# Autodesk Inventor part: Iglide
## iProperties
Author: cdotson
Shininess: 51.0
PropertySet Name: _Private Model Information
Created: 2001-02
Part Number: Iglide
Material: Default
Document SubType Name: Modeling
Designer: cdotson
Control State: 0
Master: False
Checked Out: False
PropertySet Name: Design Tracking Control
Density: 0.0
Volumn: 0.0
Area: 0.0
PropertySet Name: Model Information
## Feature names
1. Extrusion2
2. Extrusion3
3. Chamfer1
4. Chamfer2
